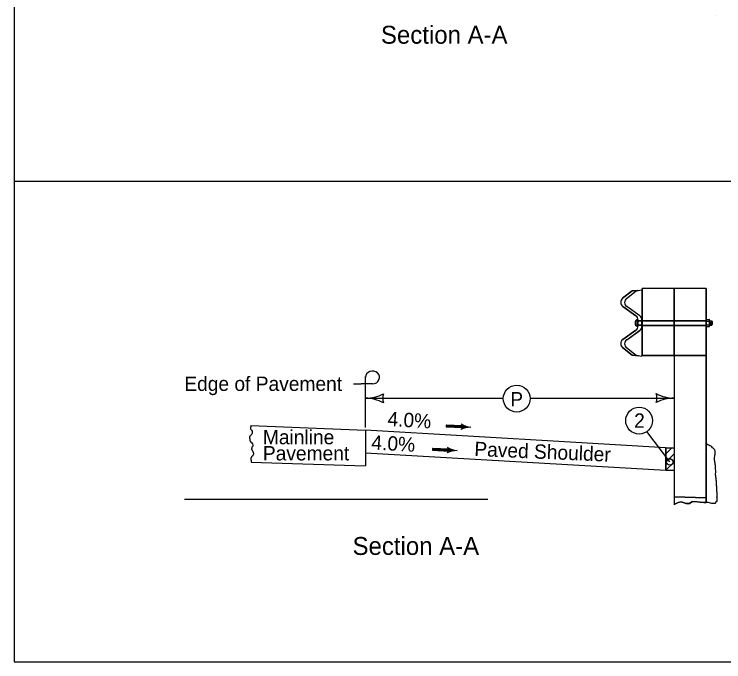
# Model space of a CAD drawing. Extents: x -1548 to 1548, y -960 to 993.
# Drawn here: x -1548 to -756, y -960 to -237 of the extents above; entities that cross this region are included whole.
import ezdxf

# ---------------------------------------------------------------- set-up
doc = ezdxf.new("R2010")
doc.units = 0
for name, color, linetype in [('dsnStdBorder', 7, 'Continuous'), ('dsnStdDimension', 7, 'Continuous'), ('dsnStdLabel', 7, 'Continuous'), ('dsnStdLineWork', 7, 'Continuous'), ('dsnStdNote', 7, 'Continuous'), ('dsnStdShading', 7, 'Continuous'), ('Level 4', 7, 'Continuous')]:
    doc.layers.add(name, color=color, linetype=linetype)

msp = doc.modelspace()

# ---------------------------------------------------------------- linework, layer by layer
at = {"layer": 'dsnStdBorder'}
for p, q in [((-1547.84, 650), (-1547.84, -960)), ((-1547.84, -960), (1547.84, -960))]:
    msp.add_line(p, q, dxfattribs=at)
at = {"layer": 'dsnStdDimension'}
for p, q in [((-1155.91, -665.87), (-1002.14, -665.87)), ((-972.16, -665.72), (-811.52, -665.72))]:
    msp.add_line(p, q, dxfattribs=at)
msp.add_circle((-987.15, -666.28), 15, dxfattribs=at)
for centre, radius, start, end in [((-1155.91, -623.37), 42.5, 270, 298.07249), ((-1120.27, -665.87), 16.42, 162.26665, 197.73335), ((-847.15, -665.72), 16.42, 342.26665, 17.73335), ((-811.52, -623.22), 42.5, 241.92751, 270), ((-1155.91, -708.37), 42.5, 61.92751, 90), ((-811.52, -708.22), 42.5, 90, 118.07249)]:
    msp.add_arc(centre, radius, start, end, dxfattribs=at)
at = {"layer": 'dsnStdLabel'}
for p, q in [((-1155.91, -662.55), (-1155.91, -641.69)), ((-1169.28, -649.71), (-1160.6, -649.71)), ((-1148.1, -649.71), (-1160.6, -649.71)), ((-1155.91, -698.49), (-1155.91, -662.55)), ((-1047.69, -697.72), (-1065.89, -696.67)), ((-1047.79, -698.66), (-1047.79, -698.66)), ((-1047.68, -696.71), (-1047.68, -696.71)), ((-1062.99, -723.81), (-1081.2, -722.76)), ((-1063.09, -724.75), (-1063.09, -724.75)), ((-1062.98, -722.8), (-1062.98, -722.8))]:
    msp.add_line(p, q, dxfattribs=at)
for points in [[(-1047.66, -696.78), (-1065.83, -695.73), (-1065.96, -697.61), (-1047.79, -698.66), (-1047.74, -697.04), (-1065.61, -695.95), (-1065.67, -697.45), (-1048.17, -698.4), (-1048.05, -697.28), (-1065.38, -696.21), (-1065.4, -697.21), (-1048.39, -698.2), (-1048.29, -697.49), (-1065.19, -696.43), (-1065.2, -697), (-1048.6, -697.93)], [(-1048.07, -695.52), (-1047.37, -696.69), (-1047.39, -698.34), (-1048.15, -699.73), (-1045.4, -698.87), (-1042.2, -698.22), (-1041.3, -698.08), (-1043.55, -697.54), (-1046.77, -696.31), (-1047.72, -695.77), (-1047.6, -699.28), (-1042.65, -698.07), (-1047.29, -696.49), (-1047.27, -698.91), (-1043.88, -697.98), (-1046.88, -697.11), (-1047.11, -698.5), (-1044.95, -698), (-1046.54, -697.49), (-1046.67, -698.15), (-1045.89, -697.98)], [(-1062.96, -722.86), (-1081.13, -721.82), (-1081.26, -723.7), (-1063.09, -724.75), (-1063.04, -723.13), (-1080.91, -722.04), (-1080.97, -723.54), (-1063.47, -724.48), (-1063.35, -723.36), (-1080.68, -722.3), (-1080.7, -723.3), (-1063.69, -724.28), (-1063.6, -723.58), (-1080.49, -722.52), (-1080.5, -723.08), (-1063.9, -724.02)], [(-1063.37, -721.61), (-1062.67, -722.78), (-1062.69, -724.42), (-1063.45, -725.82), (-1060.7, -724.96), (-1057.5, -724.31), (-1056.6, -724.17), (-1058.85, -723.62), (-1062.07, -722.39), (-1063.02, -721.86), (-1062.9, -725.37), (-1057.95, -724.16), (-1062.59, -722.57), (-1062.57, -724.99), (-1059.18, -724.06), (-1062.18, -723.2), (-1062.41, -724.59), (-1060.25, -724.08), (-1061.84, -723.58), (-1061.97, -724.24), (-1061.19, -724.07)]]:
    msp.add_lwpolyline(points, dxfattribs=at)
for centre, major_axis, start_param, end_param in [((-1148.1, -642.57), (-7.81, 0), 1.570796, 6.283185), ((-1051.46, -697.5), (3.88, 0), 5.202895, 7.237436), ((-1036.4, -678.08), (-22.17, 0), 0.954258, 1.478381), ((-1039.19, -718.5), (22.17, 0), 1.537172, 2.061295), ((-1066.76, -723.59), (3.88, 0), 5.202895, 7.237436), ((-1054.49, -744.59), (22.17, 0), 1.537172, 2.061295), ((-1051.7, -704.17), (-22.17, 0), 0.954258, 1.478381)]:
    msp.add_ellipse(centre, major_axis=major_axis, ratio=0.913811, start_param=start_param, end_param=end_param, dxfattribs=at)
at = {"layer": 'dsnStdLineWork'}
for p, q in [((-765.57, -238.77), (-765.57, -238.77)), ((-869.01, -554.27), (-858.24, -545.87)), ((-864.58, -554.5), (-853.8, -546.09)), ((-858.24, -545.87), (-851.91, -545.76)), ((-853.8, -546.09), (-847.46, -544.97)), ((-775.97, -543.51), (-847.07, -543.51)), ((-847.07, -618.16), (-847.07, -543.51)), ((-811.52, -618.16), (-811.52, -543.51)), ((-775.97, -543.51), (-775.97, -782.15)), ((-854.3, -573.8), (-868.81, -563.39)), ((-849.83, -574.04), (-864.39, -563.59)), ((-852.68, -585.91), (-852.68, -577.82)), ((-775.97, -575.21), (-775.29, -575.21)), ((-775.29, -588.54), (-775.29, -575.21)), ((-775.29, -577.84), (-772.33, -577.84)), ((-852.68, -579.51), (-847.25, -579.51)), ((-852.68, -584.18), (-847.07, -584.18)), ((-851.91, -585.25), (-851.91, -578.43)), ((-851.91, -585.25), (-851.91, -581.84)), ((-851.91, -581.84), (-851.91, -585.25)), ((-851.73, -579.51), (-847.07, -579.51)), ((-847.46, -582.06), (-847.46, -578.65)), ((-847.46, -585.47), (-847.46, -582.06)), ((-847.46, -582.06), (-847.46, -585.47)), ((-847.07, -584.51), (-775.97, -584.51)), ((-847.06, -579.18), (-775.97, -579.18)), ((-847.06, -579.51), (-775.97, -579.52)), ((-847.06, -584.18), (-775.97, -584.18)), ((-775.29, -579.86), (-772.33, -579.86)), ((-775.29, -583.9), (-772.33, -583.9)), ((-771.96, -584.91), (-771.96, -578.85)), ((-771.96, -579.54), (-769.59, -579.54)), ((-771.96, -584.21), (-769.59, -584.21)), ((-771.07, -579.54), (-771.07, -584.21)), ((-770.33, -579.54), (-770.33, -584.21)), ((-769.59, -579.54), (-769.14, -580.08)), ((-769.59, -579.54), (-769.59, -584.21)), ((-769.14, -583.68), (-769.59, -584.21)), ((-769.14, -580.08), (-769.14, -583.68)), ((-868.81, -600.29), (-854.3, -589.88)), ((-864.39, -600.53), (-849.83, -590.08)), ((-775.97, -588.54), (-775.29, -588.54)), ((-775.29, -585.92), (-772.33, -585.92)), ((-858.24, -617.81), (-869.01, -609.41)), ((-853.8, -618.03), (-864.58, -609.62)), ((-851.14, -618.5), (-858.24, -617.81)), ((-847.46, -619.15), (-853.8, -618.03)), ((-811.52, -618.16), (-847.07, -618.16)), ((-811.52, -618.16), (-811.52, -784.68)), ((-1283.66, -696.45), (-1155.91, -701.63)), ((-1155.91, -701.63), (-1155.91, -726.82)), ((-1155.91, -726.82), (-1155.91, -741.23)), ((-820.77, -727.87), (-814.03, -721.12)), ((-820.77, -727.87), (-814.03, -721.12)), ((-820.77, -727.87), (-814.03, -721.12)), ((-820.77, -727.87), (-814.03, -721.12)), ((-820.77, -721.12), (-820.77, -746.28)), ((-820.77, -721.12), (-811.54, -721.12)), ((-820.77, -737.05), (-811.54, -727.81)), ((-820.77, -737.05), (-811.54, -727.81)), ((-820.77, -737.05), (-811.54, -727.81)), ((-820.77, -737.05), (-811.54, -727.81)), ((-765.92, -727.89), (-765.92, -727.89)), ((-1283.4, -737.02), (-1156.12, -741.22)), ((-820.77, -746.28), (-811.54, -737.04)), ((-820.77, -746.28), (-811.54, -737.04)), ((-820.77, -746.28), (-811.54, -737.04)), ((-820.77, -746.28), (-811.54, -737.04)), ((-820.77, -746.28), (-811.54, -746.28)), ((-1357.97, -778.48), (-1019.46, -778.48)), ((-765.57, -786.96), (-765.57, -786.96))]:
    msp.add_line(p, q, dxfattribs=at)
for points in [[(-771.97, -584.58), (-772.02, -584.32), (-772.07, -584.14), (-772.15, -583.99), (-772.27, -583.9), (-772.19, -583.8), (-772.11, -583.57), (-772.05, -583.26), (-771.97, -582.51), (-771.97, -584.59), (-771.99, -584.45), (-772.04, -584.23), (-772.11, -584.02), (-772.23, -583.91), (-772.19, -583.82), (-772.13, -583.67), (-772.03, -583.17), (-771.99, -582.79), (-771.99, -584.39), (-772.02, -584.27), (-772.07, -584.11), (-772.19, -583.91), (-772.14, -583.74), (-772.06, -583.4), (-772.01, -583.08), (-772.01, -584.24), (-772.05, -584.11), (-772.16, -583.92), (-772.12, -583.7), (-772.07, -583.44), (-772.03, -583.27), (-772.03, -584.13), (-772.09, -584.03), (-772.14, -583.91), (-772.05, -583.46), (-772.05, -584.05), (-772.12, -583.92), (-772.07, -583.62), (-772.07, -583.98), (-772.11, -583.91), (-772.09, -583.81), (-772.09, -583.88)], [(-772.26, -579.85), (-772.19, -579.81), (-772.12, -579.71), (-772.03, -579.49), (-771.98, -579.2), (-771.97, -581.15), (-772.03, -580.64), (-772.08, -580.27), (-772.2, -579.94), (-772.26, -579.86), (-772.21, -579.85), (-772.1, -579.7), (-772.01, -579.48), (-771.99, -579.32), (-771.99, -580.86), (-772.06, -580.36), (-772.12, -580.1), (-772.22, -579.88), (-772.19, -579.86), (-772.05, -579.65), (-772.01, -579.49), (-772.01, -580.6), (-772.2, -579.89), (-772.03, -579.61), (-772.03, -580.46), (-772.18, -579.9), (-772.05, -579.68), (-772.05, -580.32), (-772.16, -579.92), (-772.07, -579.74), (-772.07, -580.16), (-772.14, -579.93), (-772.08, -579.82), (-772.08, -580.02), (-772.11, -579.95), (-772.1, -579.9)], [(-765.45, -751.73), (-765.51, -752), (-765.51, -752.2), (-765.51, -752.39), (-765.51, -752.59), (-765.51, -752.78), (-765.51, -752.98), (-765.51, -753.27), (-765.51, -753.47), (-765.41, -753.76), (-765.32, -754.05), (-765.12, -754.25), (-765.12, -754.44), (-765.02, -754.64), (-765.02, -754.83), (-765.02, -755.03), (-764.92, -755.13), (-764.92, -755.32), (-764.92, -755.52), (-764.92, -755.71), (-764.92, -755.91), (-764.92, -756.11), (-764.92, -756.4), (-764.92, -756.69), (-764.92, -756.89), (-764.92, -757.18), (-764.92, -757.38), (-764.92, -757.57), (-764.83, -757.67), (-764.83, -757.86), (-764.83, -758.06), (-764.83, -758.25), (-764.83, -758.45), (-764.83, -758.65), (-764.83, -758.84), (-764.83, -759.04), (-764.83, -759.23), (-764.83, -759.43), (-764.83, -759.62), (-764.83, -759.82), (-764.83, -760.01), (-764.83, -760.21), (-764.83, -760.4), (-764.83, -760.6), (-764.83, -760.79), (-764.83, -760.99), (-764.83, -761.19), (-764.73, -761.28), (-764.73, -761.48), (-764.73, -761.67), (-764.63, -761.77), (-764.63, -761.97), (-764.63, -762.16), (-764.53, -762.26), (-764.53, -762.46), (-764.53, -762.65), (-764.53, -762.85), (-764.53, -763.14), (-764.44, -763.43), (-764.44, -763.63), (-764.44, -763.82), (-764.44, -764.02), (-764.44, -764.21), (-764.44, -764.41), (-764.44, -764.61), (-764.44, -764.8), (-764.44, -765), (-764.44, -765.19), (-764.44, -765.39), (-764.44, -765.58), (-764.44, -765.78), (-764.44, -765.97), (-764.44, -766.17), (-764.44, -766.36), (-764.44, -766.56), (-764.44, -766.75), (-764.44, -766.95), (-764.44, -767.15), (-764.44, -767.34), (-764.44, -767.54), (-764.44, -767.73), (-764.44, -767.93), (-764.44, -768.12), (-764.44, -768.32), (-764.44, -768.51), (-764.44, -768.71), (-764.44, -768.9), (-764.44, -769.1), (-764.34, -769.2), (-764.34, -769.49), (-764.34, -769.69), (-764.24, -769.88), (-764.14, -770.17), (-764.14, -770.37), (-764.04, -770.47), (-764.04, -770.66), (-763.95, -770.76), (-763.85, -770.86), (-763.85, -771.05), (-763.85, -771.25), (-763.85, -771.44), (-763.75, -771.54), (-763.75, -771.74), (-763.75, -771.93), (-763.75, -772.13), (-763.75, -772.32), (-763.75, -772.52), (-763.75, -772.71), (-763.75, -772.91), (-763.75, -773.11), (-763.75, -773.3), (-763.75, -773.5), (-763.75, -773.69), (-763.75, -773.89), (-763.75, -774.08), (-763.75, -774.28), (-763.75, -774.47), (-763.75, -774.67), (-763.75, -774.86), (-763.75, -775.06), (-763.75, -775.26), (-763.75, -775.45), (-763.75, -775.65), (-763.75, -775.84), (-763.75, -776.04), (-763.75, -776.23), (-763.75, -776.43), (-763.75, -776.43), (-763.75, -776.13), (-763.75, -775.94), (-763.75, -775.74), (-763.75, -775.94), (-763.75, -776.13), (-763.75, -776.33), (-763.75, -776.53), (-763.75, -776.72), (-763.75, -776.92), (-763.75, -777.11), (-763.75, -777.31), (-763.75, -777.5), (-763.75, -777.7), (-763.75, -777.89), (-763.75, -778.09), (-763.75, -778.28), (-763.75, -778.48), (-763.75, -778.67), (-763.85, -778.77), (-763.85, -778.97), (-763.85, -779.16), (-763.85, -779.36), (-763.85, -779.55), (-763.85, -779.75), (-763.85, -779.95), (-763.85, -780.14), (-763.85, -780.34), (-763.85, -780.53), (-763.85, -780.73), (-763.95, -780.82), (-764.04, -781.02), (-764.14, -781.12), (-764.24, -781.22), (-764.34, -781.31), (-764.53, -781.41), (-764.73, -781.41), (-764.83, -781.51), (-764.92, -781.61), (-765.02, -781.7), (-765.22, -781.8), (-765.32, -781.9), (-765.32, -782.09), (-765.41, -782.19), (-765.41, -782.39), (-765.41, -782.58), (-765.41, -782.78), (-765.41, -782.97), (-765.41, -783.07), (-765.41, -782.88)], [(-765.45, -783.19), (-769.6, -783.31), (-773.74, -782.15), (-778.3, -782.15), (-782.54, -781.72), (-788.79, -780.98), (-791.86, -781.62), (-794.51, -783.42), (-798.22, -783.21), (-803.84, -781.62), (-807.12, -782.15), (-809.88, -783.74), (-811.52, -783.96)]]:
    msp.add_lwpolyline(points, dxfattribs=at)
for centre, radius, start, end in [((-865.53, -558.76), 5.68, 127.75002, 234.69086), ((-861.08, -558.97), 5.68, 127.75002, 234.69086), ((-850.61, -581.86), 4.54, 117.20289, 242.8461), ((-857.58, -578.43), 5.68, 360, 54.69099), ((-853.14, -578.65), 5.68, 360, 54.69099), ((-857.58, -585.25), 5.68, 305.30901, 0), ((-853.14, -585.47), 5.68, 305.30901, 0), ((-865.53, -604.92), 5.68, 125.30914, 232.24998), ((-861.08, -605.14), 5.68, 125.30914, 232.24998)]:
    msp.add_arc(centre, radius, start, end, dxfattribs=at)
for centre in [(-772.33, -578.85), (-772.33, -584.91)]:
    msp.add_ellipse(centre, major_axis=(0, -1.01), ratio=0.362258, start_param=6.283156, end_param=9.424748, dxfattribs=at)
for points in [[(-1283.66, -696.45), (-1284.16, -700.05), (-1283.12, -701.56), (-1282.25, -703.85), (-1282.86, -705.91), (-1284.76, -708.29), (-1285.28, -710.19), (-1284.76, -712.49), (-1283.9, -714.86), (-1282.86, -715.57), (-1281.47, -718.11), (-1281.48, -718.95)], [(-1281.48, -718.95), (-1281.69, -719.19), (-1281.89, -719.45), (-1282.24, -720.01), (-1282.74, -721.23), (-1282.92, -722.47), (-1282.88, -723.05), (-1282.82, -723.33), (-1282.78, -723.46), (-1282.73, -723.6), (-1282.52, -723.97), (-1282.24, -724.33), (-1281.94, -724.7), (-1281.69, -725.1), (-1281.55, -725.38), (-1281.41, -725.67), (-1281.15, -726.24), (-1280.82, -727.4), (-1280.82, -727.52), (-1280.81, -727.65), (-1280.96, -728.43), (-1281.17, -728.95), (-1281.43, -729.46), (-1281.88, -730.09), (-1282.39, -730.64), (-1282.91, -731.19), (-1283.14, -731.49), (-1283.34, -731.83), (-1283.55, -732.3), (-1283.7, -732.78), (-1283.8, -733.26), (-1283.84, -733.49), (-1283.85, -733.61), (-1283.86, -733.73), (-1283.81, -734.24), (-1283.66, -734.75), (-1283.48, -735.27), (-1283.4, -737.02)], [(-765.45, -751.73), (-765.13, -748.82), (-765.35, -743.96), (-765.79, -738.21), (-766.46, -733.79), (-766.24, -730.47), (-765.79, -726.27), (-766.46, -723.17), (-768.67, -721.18), (-770.66, -719.42), (-772.87, -718.31), (-775.08, -716.98), (-775.97, -716.32)]]:
    msp.add_spline(points, degree=3, dxfattribs=at)
at = {"layer": 'dsnStdNote'}
for centre, radius in [((-850.58, -690.83), 15), ((-816.46, -736.95), 3.58)]:
    msp.add_circle(centre, radius, dxfattribs=at)
at = {"layer": 'dsnStdShading'}
for p, q in [((-858.24, -545.87), (-869.01, -554.27)), ((-851.91, -545.76), (-858.24, -545.87)), ((-853.8, -546.09), (-851.91, -545.76)), ((-868.81, -563.39), (-854.3, -573.8)), ((-851.91, -578.43), (-851.91, -579.51)), ((-851.91, -579.51), (-847.46, -579.51)), ((-851.91, -579.51), (-851.91, -581.84)), ((-851.73, -579.51), (-851.91, -579.51)), ((-851.91, -581.84), (-851.91, -584.18)), ((-847.46, -584.18), (-851.91, -584.18)), ((-851.91, -584.18), (-851.91, -585.25)), ((-851.91, -584.18), (-847.46, -584.18)), ((-851.91, -585.25), (-851.91, -585.25)), ((-847.46, -579.51), (-851.73, -579.51)), ((-847.46, -579.51), (-847.46, -578.65)), ((-847.46, -585.47), (-847.46, -584.18)), ((-854.3, -589.88), (-868.81, -600.29)), ((-869.01, -609.41), (-858.24, -617.81)), ((-853.8, -618.03), (-864.56, -609.63)), ((-858.24, -617.81), (-851.14, -618.5)), ((-851.14, -618.5), (-853.8, -618.03))]:
    msp.add_line(p, q, dxfattribs=at)
for points in [[(-864.58, -554.5), (-864.56, -554.49), (-853.8, -546.09)], [(-811.52, -579.18), (-811.52, -543.51), (-847.07, -543.51), (-847.07, -579.18), (-847.06, -579.18), (-811.52, -579.18)], [(-775.97, -579.18), (-775.97, -575.18), (-775.97, -543.51), (-811.52, -543.51), (-811.52, -579.18), (-775.97, -579.18)], [(-864.58, -554.5), (-864.58, -554.5)], [(-849.86, -574.02), (-849.83, -574.04), (-864.37, -563.61)], [(-864.37, -563.61), (-864.37, -563.61)], [(-851.91, -581.84), (-851.91, -581.84)], [(-851.91, -585.25), (-851.91, -585.25)], [(-847.46, -584.18), (-847.46, -582.06), (-847.46, -579.51)], [(-847.07, -579.51), (-847.07, -584.18), (-847.06, -584.18), (-811.52, -584.18), (-811.52, -579.52), (-847.06, -579.51), (-847.07, -579.51)], [(-847.07, -584.51), (-847.07, -618.16), (-811.52, -618.16), (-811.52, -584.51), (-847.07, -584.51)], [(-775.97, -584.18), (-775.97, -579.52), (-811.52, -579.52), (-811.52, -584.18), (-775.97, -584.18)], [(-775.97, -618.16), (-775.97, -588.51), (-775.97, -584.51), (-811.52, -584.51), (-811.52, -618.16), (-775.97, -618.16)], [(-864.39, -600.53), (-864.37, -600.51), (-849.86, -590.1), (-849.83, -590.08)], [(-849.83, -590.08), (-849.83, -590.08)], [(-864.39, -600.53), (-864.39, -600.53)], [(-864.56, -609.63), (-864.56, -609.63)], [(-775.97, -777.1), (-775.97, -618.16), (-811.52, -618.16), (-811.52, -721.12), (-811.52, -727.81), (-811.52, -727.81), (-811.52, -727.81), (-811.52, -737.04), (-811.52, -737.04), (-811.52, -737.04), (-811.52, -746.18), (-811.52, -746.18), (-811.52, -746.18), (-811.52, -753.11), (-811.52, -775.94), (-775.97, -777.1)], [(-775.97, -777.1), (-811.52, -775.94), (-811.52, -783.96), (-809.88, -783.74), (-807.12, -782.15), (-803.84, -781.62), (-798.22, -783.21), (-794.51, -783.42), (-791.86, -781.62), (-788.79, -780.98), (-782.54, -781.72), (-778.3, -782.15), (-775.97, -782.15), (-775.97, -777.1)]]:
    msp.add_lwpolyline(points, dxfattribs=at)
msp.add_lwpolyline([(-820.77, -746.28), (-820.77, -741.81), (-820.77, -730.06), (-820.77, -721.12), (-927.46, -714.92), (-1155.91, -701.63), (-1155.91, -726.82)], close=True, dxfattribs=at)
for centre, start, end in [((-865.53, -558.76), 127.75002, 234.69086), ((-861.08, -558.97), 127.94699, 234.69086), ((-857.58, -578.43), 360, 54.69099), ((-853.14, -578.65), 360, 54.69099), ((-857.58, -585.25), 305.30901, 0), ((-853.14, -585.47), 305.67034, 360), ((-865.53, -604.92), 125.30914, 232.24998), ((-861.08, -605.14), 125.66008, 232.24998)]:
    msp.add_arc(centre, 5.68, start, end, dxfattribs=at)
at = {"layer": 'Level 4'}
for p, q in [((607.73, -424), (-1547.84, -424)), ((-816.46, -736.95), (-841.84, -703.02))]:
    msp.add_line(p, q, dxfattribs=at)

# ---------------------------------------------------------------- texts
at = {"layer": 'dsnStdDimension'}
msp.add_text('P', height=16, dxfattribs=at).set_placement((-994.38, -674.96))
at = {"layer": 'dsnStdLabel'}
for s, height, p in [('Section A-A', 20, (-1138.65, -270.22)), ('Edge of Pavement', 16, (-1358.04, -657.71)), ('Mainline', 16, (-1270.38, -717.26)), ('Pavement', 16, (-1270.38, -735.26)), ('Section A-A', 20, (-1170.33, -840.72))]:
    msp.add_text(s, height=height, dxfattribs=at).set_placement(p)
for s, rotation, p in [('4.0%', 356.69917, (-1131.72, -696.77)), ('4.0%', 356.69917, (-1149.67, -722.95)), ('Paved Shoulder ', 357.5923, (-1034.72, -730.3))]:
    msp.add_text(s, height=16, rotation=rotation, dxfattribs=at).set_placement(p)
at = {"layer": 'dsnStdNote'}
msp.add_text('2', height=16, dxfattribs=at).set_placement((-856.2, -698.83))

doc.saveas('drawing.dxf')
